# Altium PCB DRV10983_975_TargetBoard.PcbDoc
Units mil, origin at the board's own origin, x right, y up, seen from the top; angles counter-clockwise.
Board outline 2000 x 1750 mil, 2 copper layers (Top Layer, Bottom Layer), stack 64.8 mil thick; 30 components, 21 nets, 96 pads, 54 vias.
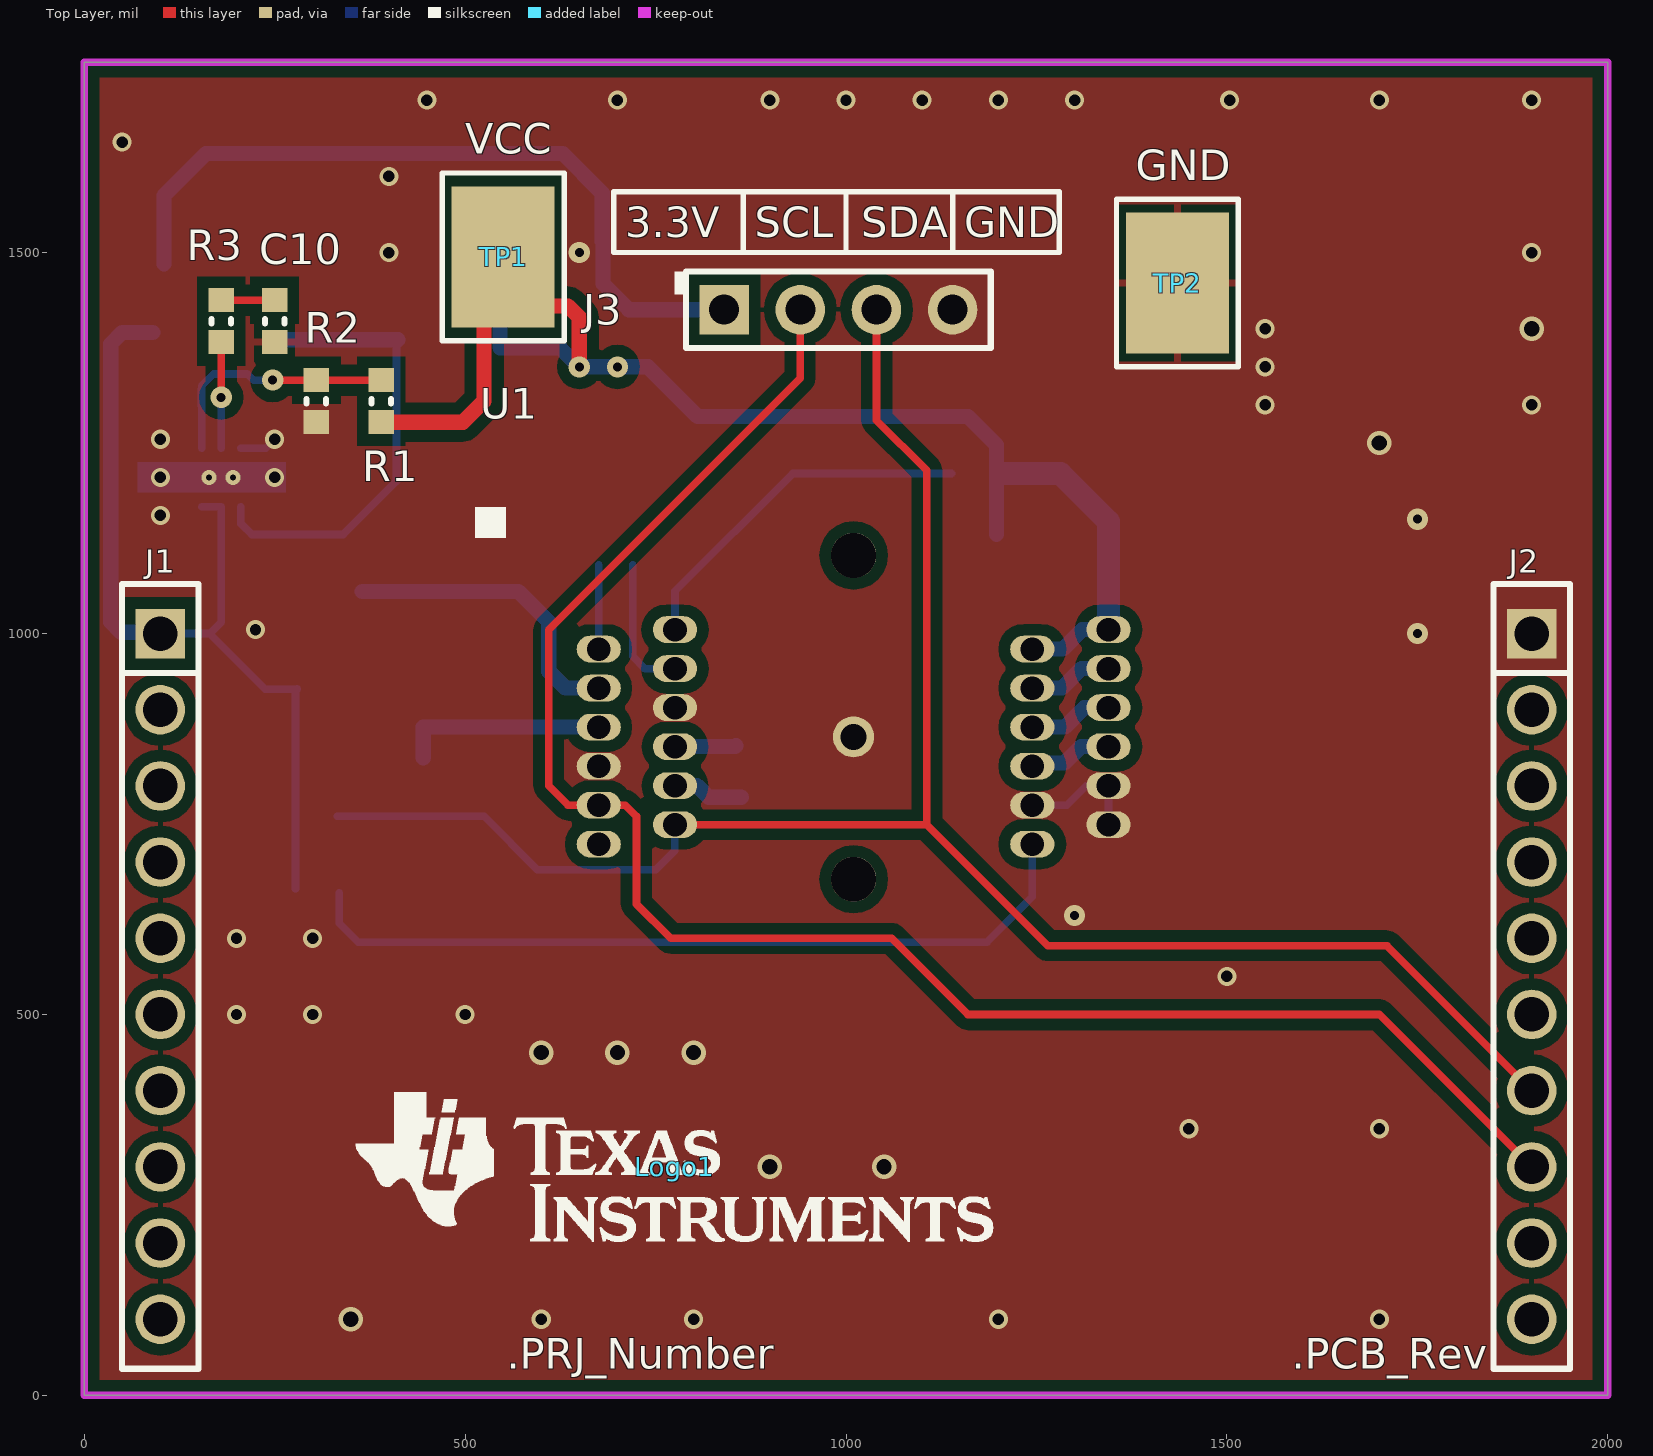
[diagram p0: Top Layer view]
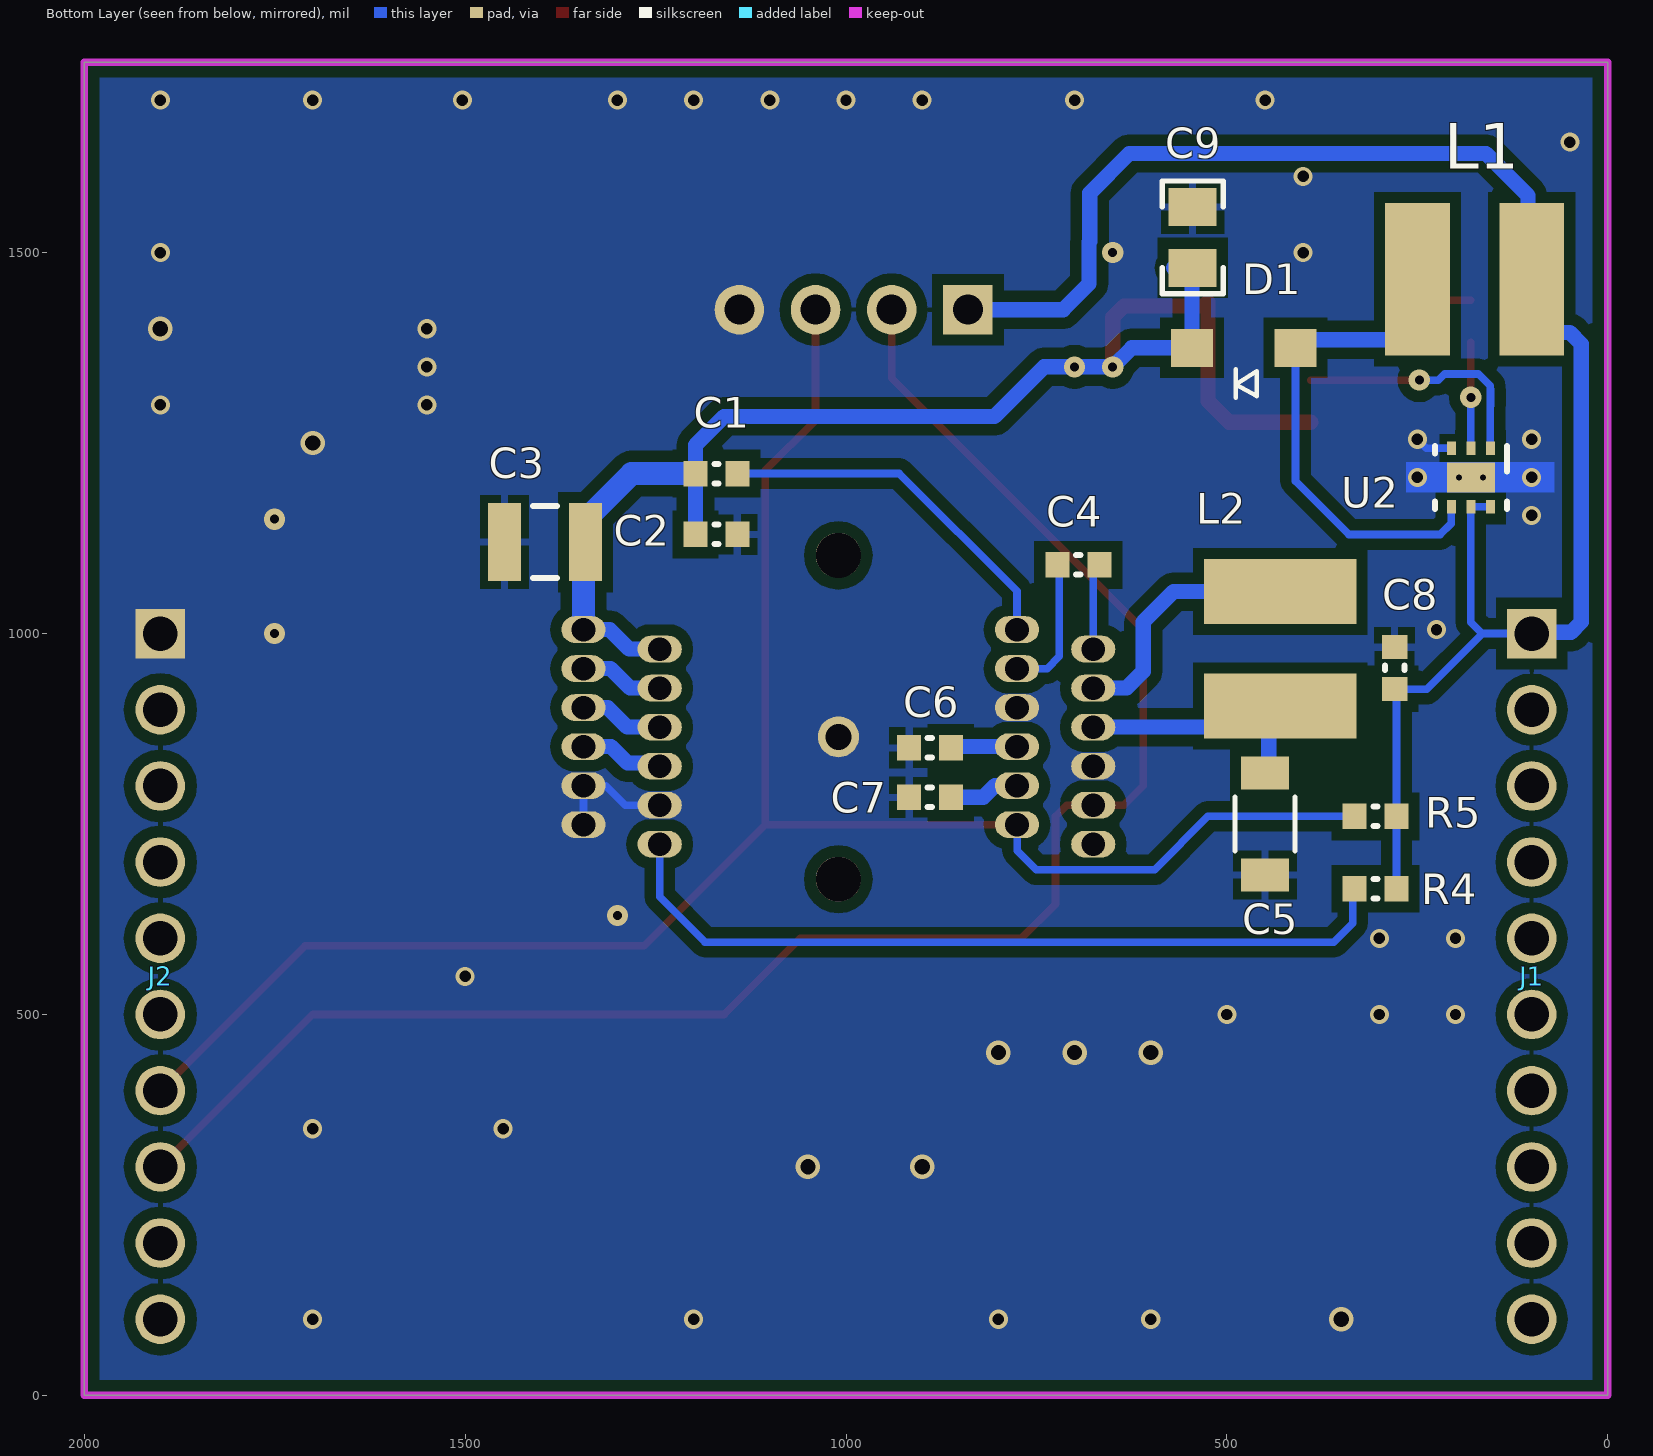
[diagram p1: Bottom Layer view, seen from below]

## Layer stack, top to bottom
Top Layer: signal copper 2.8
Dielectric: core 59.2, FR-4, Dk 4.8
Bottom Layer: signal copper 2.8

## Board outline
0,0 2000,0 2000,1750 0,1750

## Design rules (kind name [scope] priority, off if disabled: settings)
AcuteAngle [All] p1: minimum=4.50000000000000E+0001 checktracksonly=FALSE
AssemblyTestPointUsage [All] p1: valid=2
Clearance Clearance_BoardEdge_MountingHoles [OnCopper and InComponentClass('Mounting Holes') vs IsKeepOut] p1: gap=15
Clearance Clearance_BoardEdge_Poly [OnCopper and InPoly vs IsKeepOut] p2: gap=15
Clearance Clearance_BoardEdge [OnCopper and Not InComponentClass('Logo') and not InComponentClass('FiducialMark') and not InRegion(1000,500,4000,800) and Not IsKeepout vs IsKeepOut] p3: gap=15
Clearance Clearance_Poly [InPolygon] p4: gap=15
Clearance [All] p5: gap=7
ComponentClearance ComponentClearance_Logo [InComponentClass(Logo)] p1: gap=10 collisioncheckmode=3 verticalgap=10 showdistances=FALSE
ComponentClearance ComponentClearance_ScrewToNut [(HasFootprint('NY PMS 440 0025 PH')) vs (HasFootprint('Keystone_1902C'))] p2: gap=5 collisioncheckmode=3 verticalgap=10 showdistances=FALSE
ComponentClearance ComponentClearance_MountingHoles [InComponentClass('Mounting Holes')] p3: gap=250 collisioncheckmode=3 verticalgap=100000 showdistances=FALSE
ComponentClearance ComponentClearance_SmallPassives [HasFootprint('0201*') or HasFootprint('0402*') or HasFootprint('0508') or HasFootprint('0603*') or HasFootprint('0612') or HasFootprint('0805*') or HasFootprint('0815*') or HasFootprint('0830*') or HasFootprint('1206*') or HasFootprint('1210*') or HasFootprint('1808*') or HasFootprint('1812*') or HasFootprint('1825*') or HasFootprint('2010*') or HasFootprint('2220*') or HasFootprint('2225*') or HasFootprint('2512*') or HasFootprint('2728*') or HasFootprint('3518*') vs HasFootprint('0201*') or HasFootprint('0402*') or HasFootprint('0508') or HasFootprint('0603*') or HasFootprint('0612') or HasFootprint('0805*') or HasFootprint('0815*') or HasFootprint('0830*') or HasFootprint('1206*') or HasFootprint('1210*') or HasFootprint('1808*') or HasFootprint('1812*') or HasFootprint('1825*') or HasFootprint('2010*') or HasFootprint('2220*') or HasFootprint('2225*') or HasFootprint('2512*') or HasFootprint('2728*') or HasFootprint('3518*')] p4: gap=10 collisioncheckmode=3 verticalgap=10 showdistances=FALSE
ComponentClearance ComponentClearance_THtoSMT [IsThruComponent vs IsSMTComponent] p5: gap=100 collisioncheckmode=3 verticalgap=30 showdistances=FALSE
ComponentClearance ComponentClearance_THtoTH [IsThruComponent vs IsThruComponent] p6: gap=0 collisioncheckmode=3 verticalgap=0 showdistances=FALSE
ComponentClearance [All] p7: gap=10 collisioncheckmode=3 verticalgap=10 showdistances=FALSE
DiffPairsRouting [All] p1: maxlimit=100 minlimit=10 mostfreqgap=10 maxuncoupledlength=1000
FabricationTestPointUsage TestPointUsage [All] p1: valid=2 allowmultiple=FALSE
FabricationTestpoint Testpoint [All] p1: side=3 testpointundercomponent=TRUE minsize=40 maxsize=100 preferedsize=60 minholesize=0 maxholesize=40 preferedholesize=32 testpointgrid=1 allowsidetop=TRUE allowsidebottom=TRUE usegrid=TRUE gridtolerance=0.01
FanoutControl Fanout_LCC [IsLCC] p1: bgadir=Out bgaviamode=Centered fanoutstyle=Auto fanoutdirection=Alternating viagrid=1 // Fanout_LCC (Default Rule)
FanoutControl Fanout_BGA [IsBGA] p2: bgadir=Out bgaviamode=Centered fanoutstyle=Auto fanoutdirection=Alternating viagrid=1 // Fanout_BGA (Default Rule)
FanoutControl Fanout_Default [All] p4: bgadir=Out bgaviamode=Centered fanoutstyle=Auto fanoutdirection=Alternating viagrid=1 // Fanout_Default (Default Rule)
FanoutControl Fanout_Small [(CompPinCount < 5)] p5: bgadir=Out bgaviamode=Centered fanoutstyle=Auto fanoutdirection=OutThenIn viagrid=1 // Fanout_Small (Default Rule)
HoleSize [All] p1: absolutevalues=TRUE maxlimit=251 minlimit=8 maxpercent=80.000 minpercent=20.000
MinimumAnnularRing [All] p1: minimumring=5
MinimumSolderMaskSliver MinimumSolderMaskSliver_Logo [InComponentClass('Logo') vs InComponentClass('Logo')] p1: minsoldermaskwidth=0.7
MinimumSolderMaskSliver [All] p2: minsoldermaskwidth=3
PlaneClearance [All] p1: clearance=15
PlaneConnect [All] p1: planeconnectstyle=Relief reliefexpansion=10 reliefentries=4 reliefconductorwidth=10 reliefairgap=10
PolygonConnect PolygonConnect_1 [IsNamedPolygon('GND_TOP') or IsNamedPolygon('GND_BOT') vs Not (InComponent('U1') or InComponent('J2') or InComponent('J3') or InComponent('J5') or InComponent('C1') or InComponent('R1') or InComponent('R2') or IsStitchingVia or IsVia)] p1: connectstyle=Relief reliefconductorwidth=10 reliefentries=4 polygonreliefangle="90 Angle" airgapwidth=10
PolygonConnect [All] p2: connectstyle=Direct reliefconductorwidth=10 reliefentries=4 polygonreliefangle="90 Angle" airgapwidth=10
RoutingVias [All] p1: holewidth=15 width=25 viastyle="Through Hole" minholewidth=8 minwidth=20 maxholewidth=40 maxwidth=65
SMDToCorner [All] p1: distance=30000
SilkToSilkClearance [All] p1: silktosilkclearance=5
SilkscreenOverComponentPads [All] p1: minsilkscreentomaskgap=5
SolderMaskExpansion [All] p1: expansion=3
Width [All] p1: maxlimit=100 minlimit=6 preferedwidth=10 checkconnectedcopper=TRUE
13 further rules are at their usual default settings.

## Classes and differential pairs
component class Hardware_ANSI-B: !PCB Logo1 ZZ1 ZZ2 ZZ3 ZZ4
component class AssemblyNote: ZZ1 ZZ2 ZZ3 ZZ4
component class Header: J3
component class DRV10983_975_TargetBoard: C1 C2 C3 C4 C5 C6 C7 C8 C9 C10 D1 J1 J2 J3 L1 L2 R1 R2 R3 R4 R5 TP1 TP2 U1 U2
component class Logo: Logo1

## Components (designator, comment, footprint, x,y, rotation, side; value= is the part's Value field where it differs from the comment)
C1 "C1608X7R1H104K" 0603L 1170,1210 r180 bottom
C2 "C1608X7R1H104K" 0603L 1170,1130 r180 bottom
C3 "GRM32ER71H475KA88L" 1210L 1395,1120 r180 bottom
C4 "C1608X7R1H104K" 0603L 695,1090 r0 bottom
C5 "CGA5L3X5R1H106K160AB" 1206_190 450,750 r90 bottom
C6 "GRM188R61H105KAALD" 0603L 890,850 r180 bottom
C7 "GRM188R61H105KAALD" 0603L 890,785 r180 bottom
C8 "0603ZD475KAT2A" 0603L 280,955 r90 bottom
C9 "C2012X5R1H475K125AB" 0805_HV 545,1520 r90 bottom
C10 "C1608X7R1H103K" 0603L 250,1410 r270 top
D1 "D_SCHOT_MBR0540T" SOD-123 475,1375 r180 bottom
J1 "CRD-081413-B-T" CONN_SSW-110-23-F-S 100,1000 r90 bottom
J2 "CRD-081413-B-T" CONN_SSW-110-23-F-S 1900,1000 r90 bottom
J3 "5-146278-4" TE_5-146278-4 990,1425 r0 top
L1 "VLCF5020T-100M1R1-1" IND_VLCF5020T 175,1465 r0 bottom
L2 "VLCF5020T-100M1R1-1" IND_VLCF5020T 430,980 r90 bottom
Logo1 "Texas Instruments" TI_Stacked_Overlay_Small 775,300 r0 top
R1 "RC0603FR-07178KL" 0603L 390,1305 r270 top
R2 "CRCW060310K0FKEA" 0603L 305,1305 r90 top
R3 "CRCW060310K0FKEA" 0603L 180,1410 r270 top
R4 "CRCW06035K10JNEA" 0603L 305,665 r180 bottom
R5 "CRCW06035K10JNEA" 0603L 305,760 r180 bottom
TP1 "5016" Testpoint_Keystone_Compact 550,1494.41 r90 top
TP2 "5016" Testpoint_Keystone_Compact 1435,1460 r90 top
U1 "OTS-24(28)-0.65-02" RECEPTACLE_OTS_24(28)-0.65-01_WCENTERPIN 1010,890 r0 top
U2 "TPS61170DRV" DRV0006A 180,1205 r270 bottom
ZZ1 "This Assembly Note is for PCB labels only" AssemblyNoteLabel 170,2750 r0 top
ZZ2 "These assemblies are ESD sensitive, ESD precautions shall be observed." AssemblyNote 170,2540 r0 top
ZZ3 "These assemblies must be clean and free from flux and all contaminants. Use of no clean flux is not acceptable." AssemblyNote 170,2330 r0 top
ZZ4 "These assemblies must comply with workmanship standards IPC-A-610 Class 2, unless otherwise specified." AssemblyNote 170,2135 r0 top

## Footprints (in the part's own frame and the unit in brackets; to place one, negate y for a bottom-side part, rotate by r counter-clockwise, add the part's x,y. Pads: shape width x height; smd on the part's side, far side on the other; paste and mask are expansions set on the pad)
0603L [mm] "0603 from SM-752 data"
  rect 0.8x0.85 smd: 1(-0.7,0) 2(0.7,0)
  silkscreen extent -0.07,-0.33 0.07,0.33, body extent -0.87,-0.47 0.87,0.47, height 0.85
0805_HV [mil] "0805 with 30mil clearance between pads"
  rect 50x63 smd: 1(-40,0) 2(40,0)
  silkscreen extent -74,-40 74,40, body extent -43,-29 43,29, height 43
1206_190 [mm] "1206_190"
  rect 1.1x1.6 smd: 1(-1.7,0) 2(1.7,0)
  silkscreen extent -0.9,-1 0.9,1, body extent -1.75,-0.95 1.75,0.95, height 1.9
1210L [mm] "1210 from SM-752 data"
  rect 1.1x2.6 smd: 1(-1.35,0) 2(1.35,0)
  silkscreen extent -0.4,-1.2 0.4,1.2, body extent -1.7,-1.35 1.7,1.35, height 1.35
AssemblyNote [mil] "Assembly Note"
AssemblyNoteLabel [mil] "Assembly Note for PCB Labels"
CONN_SSW-110-23-F-S [mm] "SAMTEC"
  rect 1.65x1.65 hole 1.15: 1(0,0)
  round 1.65 hole 1.15: 2(-2.54,0) 3(-5.08,0) 4(-7.62,0) 5(-10.16,0) 6(-12.7,0) 7(-15.24,0) 8(-17.78,0) 9(-20.32,0) 10(-22.86,0)
  body extent -24.43,-1.27 1.57,1.27, height 8.59
DRV0006A [mm] "SON, 6-Leads, Body 2x2mm, Pitch 0.65mm, Thermal Pad 1.6x1mm, TI Recommended"
  rect 0.45x0.3 smd: 1(-0.975,0.65) 2(-0.975,0) 3(-0.975,-0.65) 4(0.975,-0.65) 5(0.975,0) 6(0.975,0.65)
  rect 1x1.6 smd paste-0.5: 7(0,0)
  silkscreen extent -1.05,-1.2 1.05,1.2, body extent -1.05,-1.05 1.05,1.05, height 0.81
IND_VLCF5020T [mil]
  rect 85x200 smd: 1(-75,0) 2(75,0)
RECEPTACLE_OTS_24(28)-0.65-01_WCENTERPIN [mil]
  oval 58x35 hole 31: 1(-234.5,115.2) 2(-334.5,89.6) 3(-234.5,64) 4(-334.5,38.4) 5(-234.5,12.8) 6(-334.5,-12.8) 7(-234.5,-38.4) 8(-334.5,-64) 9(-234.5,-89.6) 10(-334.5,-115.2) 11(-234.5,-140.8) 12(-334.5,-166.4) 13(234.5,-166.4) 14(334.5,-140.8) 15(234.5,-115.2) 16(334.5,-89.6) 17(234.5,-64) 18(334.5,-38.4) 19(234.5,-12.8) 20(334.5,12.8) 21(234.5,38.4) 22(334.5,64) 23(234.5,89.6) 24(334.5,115.2)
  round 59 hole 59 unplated: 25(0,-212.5) 26(0,212.5)
  round 54 hole 34: 27(0,-25.59)
  silkscreen extent -496,236 -456,276
SOD-123 [mil]
  rect 55x50 smd: 1(-71,0) 2(65,0)
  silkscreen extent -14,-66 14,-28
TE_5-146278-4 [mm] "TE CONNECTIVITY"
  rect 1.65x1.65 hole 1: 1(-3.81,0)
  round 1.65 hole 1: 2(-1.27,0) 3(1.27,0) 4(3.81,0)
  silkscreen extent -5.46,-1.27 5.08,1.27, body extent -4.95,-1.17 4.95,1.17, height 8.13
Testpoint_Keystone_Compact [mil] "Compact SMT test point"
  rect 185x135 smd: 1(0,0)
  silkscreen extent -110,-80 110,80, body extent -75,-56 75,56, height 91
TI_Stacked_Overlay_Small [mil]
  silkscreen extent -418,-98 418,98

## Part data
C1 C2 C4: "CAP, CERM, 0.1uF, 50V, +/-10%, X7R, 0603"
C3: "CAP, CERM, 4.7uF, 50V, +/-10%, X7R, 1210"
C5: "CAP, CERM, 10uF, 50V, +/-10%, X5R, 1206_190"
C6 C7: "CAP, CERM, 1uF, 50V, +/-10%, X5R, 0603"
C8: "CAP, CERM, 4.7uF, 10V, +/-10%, X5R, 0603"
C9: "CAP, CERM, 4.7uF, 50V, +/-10%, X5R, 0805"
C10: "CAP, CERM, 0.01uF, 50V, +/-10%, X7R, 0603"
D1: "Diode, Schottky, 0.5A, 40V"
J1 J2: library part SSW-110-23-F-S, "Connector, Receptacle, 100mil, 10x1, TH"
J3: "Header, 100mil, 4x1, Tin, TH"
L1 L2: library part IND_VLCF5020T-SERIES, "Inductor, SMT, yyA, zzmilliohm"
Logo1: library part TI_Logo, "Texas Instrument Corporate Signature"
R1: "RES, 178k ohm, 1%, 0.1W, 0603"
R2 R3: "RES, 10.0k ohm, 1%, 0.1W, 0603"
R4 R5: "RES, 5.1k ohm, 5%, 0.1W, 0603"
TP1 TP2: "Test Point, Compact, SMT"
U1: library part Receptacle_OTS-24(28)-065-01, "Socket, 24 pin HTTOP no center pin"
U2: "1.2A High Voltage Boost Converter in 2x2mm QFN Package, DRV0006A"
ZZ1: library part AssemblyNoteLabel
ZZ2 ZZ3 ZZ4: library part AssemblyNote

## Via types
v1: diameter 25, hole 15, Top Layer to Bottom Layer, tented both sides, 36 vias
v2: diameter 27.81, hole 11.81, Top Layer to Bottom Layer, 8 vias
v3: diameter 32, hole 20, Top Layer to Bottom Layer, 8 vias
v4: diameter 19.68, hole 7.87, Top Layer to Bottom Layer, 2 vias

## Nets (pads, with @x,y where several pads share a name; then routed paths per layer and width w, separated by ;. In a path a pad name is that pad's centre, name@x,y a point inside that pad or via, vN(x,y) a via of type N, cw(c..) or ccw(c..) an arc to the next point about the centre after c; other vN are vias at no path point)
3.3V: C8.1 J1.1 J3.1 L1.1 R4.2 R5.2 U2.5 U2.6 | length 2150.9
  Bottom Layer w10: J1.1 165,1000 ; U2.6 U2.5 180,1015 165,1000 ; R4.2 R5.2 277.44,924.88 C8.1@279.51,926.95 ; C8.1@280,926.95 C8.1@279.51,926.95 ; C8.1 C8.1@279.51,926.95 ; 165,1000 238.05,926.95 C8.1@279.51,926.95
  Bottom Layer w20: J1.1@80,1001.61 48.39,1001.61 35,1015 35,1380 50,1395 L1.1@90,1395 ; L1.1@105,1485 105,1575 160,1630 628.28,1630 680,1578.28 680,1514.61 680.91,1513.71 680.91,1459.09 715,1425 J3.1
CPN: C4.2 U1.3 | length 182.1
  Bottom Layer w10: C4.2@720,1090 720,970 736,954 U1.3
CPP: C4.1 U1.2 | length 110.4
  Bottom Layer w10: U1.2 C4.1@675.5,1090
FG: U1.12
GND: C2.2 C3.1 C5.1 C6.1 C7.1 C8.2 C9.2 C10.2 J2.1 J3.4 R2.1 TP2.1 U1.5 U1.8 U1.14 U1.15 U1.16 U1.27 U2.3 U2.7 | length 224.9
  Bottom Layer w10: v4(195.75,1205) U2.7@205.59,1214.84 ; U2.3 238.39,1243.39 v1(250,1255) ; U1.15 1289.8,774.8 1315.4,800.4 U1.16 U1.14
  other v1: 600,100 800,100 1200,100 1700,100 1450,350 1700,350 200,500 300,500 500,500 1500,550 200,600 300,600 225,1005 100,1155 100,1205 250,1205 100,1255 1550,1300 1900,1300 1550,1350 1550,1400 400,1500 1900,1500 400,1600 50,1645 450,1700 700,1700 900,1700 1000,1700 1100,1700 1200,1700 1300,1700 1503.62,1700 1700,1700 1900,1700
  other v2: 1300,630 1750,1000 1750,1150 650,1500
  other v3: 350,100 900,300 1050,300 600,450 700,450 800,450 1700,1250 1900,1400
  other v4: 164.25,1205
NetC10_1: C10.1 R3.1 | length 70
  Top Layer w10: R3.1 C10.1
NetD1_2: D1.2 L1.2 U2.4 | length 581.6
  Bottom Layer w10: U2.4 205.59,1144.41 220,1130 340,1130 410,1200 D1.2
  Bottom Layer w20: L1.2@266.85,1385.5 D1.2@411.85,1385.5
NetR1_1: R1.1 R2.2 U2.1 | length 327.3
  Top Layer w10: v2(247.56,1332.56) R2.2 R1.1
  Bottom Layer w10: U2.1 154.41,1298.95 154.09,1299.27 154.09,1320.73 154.41,1321.05 154.41,1325 170.08,1340.67 214.33,1340.67 222.44,1332.56 v2(247.56,1332.56)
NetR3_2: R3.2 U2.2 | length 139.1
  Top Layer w10: v2(180,1310) R3.2
  Bottom Layer w10: U2.2 v2(180,1310)
SCL: J2.8 J3.2 U1.10 | length 2326.2
  Top Layer w10: J3.2 940,1335 610,1005 610,800 635.2,774.8 710.2,774.8 725,760 725,645 770,600 1060,600 1160,500 1700,500 J2.8
SDA: J2.7 J3.3 R5.1 U1.11 | length 2598.8
  Top Layer w10: 885.85,749.2 U1.11 1105.8,749.2 ; J3.3 1040,1280 1105.8,1214.21 1105.8,749.2 ; J2.7 1710,590 1265,590 1105.8,749.2
  Bottom Layer w10: R5.1 525,760 595,690 750,690 775,715 775,748.7 U1.11
SPEED: R4.1 U1.13 | length 1053.6
  Bottom Layer w10: R4.1@335,660 335,620 360,595 1185,595 1244.5,654.5 U1.13
SW: L2.2 U1.4 | length 401
  Bottom Layer w20: L2.2@365,1055 570,1055 610,1015 610,950 631.6,928.4 U1.4
U: U1.17 U1.18 | length 110.6
  Bottom Layer w20: U1.17 1248.5,830 1286.8,830 1308.4,851.6 U1.18
V: U1.19 U1.20 | length 110.6
  Bottom Layer w20: U1.19 1287.2,877.2 1312.8,902.8 U1.20
V1P8: C6.2 U1.7 | length 80.5
  Bottom Layer w20: U1.7 854.61,851.6 C6.2@855.57,852.56
V3P3: C7.2 U1.9 | length 93.3
  Bottom Layer w20: U1.9 804.6,800.4 820,785 C7.2
VCC: C1.1 C2.1 C3.2 C9.1 D1.1 R1.2 TP1.1 U1.23 U1.24 | length 1813.7
  Top Layer w20: R1.2 497.44,1277.44 525,1305 525,1435 530,1430 635,1430 650,1415 v2(650,1350)
  Bottom Layer w20: C9.1@546,1456 D1.1 625,1375 v2(650,1350) 740,1350 805,1285 1160,1285 1197.56,1247.44 C1.1 C2.1 ; C9.1@557.5,1467.5 C9.1@570,1480 ; U1.23 1284.6,979.6 1310.2,1005.2 U1.24
  Bottom Layer w30: C1.1@1204.43,1210 1281.38,1210 1344.5,1146.88 U1.24
  other v2: 700,1350
VCP: C1.2 U1.1 | length 477.3
  Bottom Layer w10: U1.1 775.5,1055.5 930,1210 C1.2@1138.5,1210
VREG: C5.2 L2.1 U1.6 | length 270.8
  Bottom Layer w20: C5.2@445,836.93 445,877.2 U1.6
W: U1.21 U1.22 | length 110.6
  Bottom Layer w20: U1.21 1283.4,928.4 1309,954 U1.22
pads on no net: J1.2 J1.3 J1.4 J1.5 J1.6 J1.7 J1.8 J1.9 J1.10 J2.2 J2.3 J2.4 J2.5 J2.6 J2.9 J2.10 U1.25 U1.26

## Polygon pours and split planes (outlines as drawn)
GND on Bottom Layer "GND_BOT" (solid, remove dead copper, pour order 5): 0,0 2000,0 2000,1750 0,1750
GND on Top Layer "GND_TOP" (solid, remove dead copper, pour order 32): 0,1750 2000,1750 2000,0 0,0

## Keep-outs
Keep-Out Layer:
  the board outline again, w10
  text ".Layer_Name" at 577,-858.49 h60

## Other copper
Top Layer:
  text ".Layer_Name" at 577,-858.49 h60
Bottom Layer:
  rectangle net GND: 70,1185 265,1225
  text ".Layer_Name" at 577,-858.49 h60

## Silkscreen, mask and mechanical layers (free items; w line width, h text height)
Top Overlay:
  lines w7: 865,1500 865,1580 ; 1000,1500 1000,1580 ; 1140,1500 1140,1580 ; 695,1500 695,1580 1280,1580 1280,1500 695,1500
  text "VCC" at 500,1630 h40
  text "GND" at 1380,1595 h40
  text "3.3V" at 710,1520 h40
  text "SCL" at 880,1520 h40
  text "SDA" at 1020,1520 h40
  text "GND" at 1155,1520 h40
  text ".PRJ_Number" at 555,35 h40
  text ".PCB_Rev" at 1585,35 h40
  text ".Layer_Name" at 577,-858.49 h60
Bottom Overlay:
  text ".Layer_Name" at 577,-858.49 h60
Top Paste:
  text ".Layer_Name" at 577,-858.49 h60
Bottom Paste:
  text ".Layer_Name" at 577,-858.49 h60
Top Solder:
  text ".Layer_Name" at 577,-858.49 h60
  text ".Layer_Name" at 577,-858.49 h60
Bottom Solder:
  text ".Layer_Name" at 577,-858.49 h60
Drill Guide:
  text ".Layer_Name" at 577,-858.49 h60
M1 Board Outline:
  the board outline again, w10
  text ".Layer_Name" at 577,-858.49 h60
M2 Board Dimensions:
  rectangle: 124.5,-410.5 499.5,-285.5
  rectangle: -0.5,-285.5 124.5,-160.5
  lines w7: -0.5,-285.5 999.5,-285.5 ; 124.5,-410.5 124.5,-160.5 ; 249.5,-410.5 249.5,-160.5 ; 499.5,-410.5 499.5,-160.5 ; 749.5,-410.5 749.5,-160.5 ; -0.5,-410.5 -0.5,-160.5 999.5,-160.5 999.5,-410.5 -0.5,-410.5
  lines w10: -0.5,-475.5 -0.5,-455.5 ; 59.5,-485.5 -0.5,-465.5 ; 59.5,-445.5 -0.5,-465.5 ; 223.58,-465.5 -0.5,-465.5 ; 775.42,-465.5 999.5,-465.5 ; 939.5,-485.5 999.5,-465.5 ; 939.5,-445.5 999.5,-465.5 ; 999.5,-475.5 999.5,-455.5
  text "1000 (mil)" at 233.58,-501.49 h60
  text ".Layer_Name" at 577,-858.49 h60
M3 3D STEP Top:
  text ".Layer_Name" at 577,-858.49 h60
M4 3D STEP Bottom:
  text ".Layer_Name" at 577,-858.49 h60
M5 Assembly Top:
  lines w7: 2319,170.5 3444,170.5 ; 2319,293 3441.5,293 ; 2634,50.5 2634,413 ; 3019,50.5 2319,50.5 ; 3019,413 2319,413 ; 2319,50.5 2319,413 ; 2319,50.5 3444,50.5 3444,413 2319,413
  lines w10: -292,-930.17 6308,-930.17 ; -292,-726.83 6310,-726.83 ; -292,-523.5 -292,-1133.5 3713,-1133.5 6310,-1133.5 6310,-523.5 -291.5,-523.5 -291.5,-1133.5 1284,-1133.5 ; 2173,-1133.5 2173,-523.5 ; 3440,-726.83 3440,-523.5 ; 4280,-726.83 4280,-523.5 ; 4902,-1140 4902,-937.17
  text "TABLE 1" at 2706.5,448 h40
  text "Variant" at 2344,338 h40
  text "Label text" at 2779,338 h40
  text "001" at 2411.5,218 h40
  text "ChangeMe!" at 2689,215.5 h40
  text "002" at 2411.5,93 h40
  text "ChangeMe!" at 2684,90.5 h40
  text "COMPONENTS MARKED 'DNP' SHOULD NOT BE POPULATED." at 1153.5,-318.5 h60
  text "ASSEMBLY VARIANT:" at 1153,-434 h60
  text ".VariantName" at 2189,-434 h60
  text "PCB VIEWED FROM TOP SIDE" at -228.5,-655.67 h60
  text "BOARD #:" at 2248,-655.67 h60
  text ".PRJ_Number" at 2793.5,-655.67 h60
  text "REV:" at 3638,-655.67 h60
  text ".PCB_Rev" at 3929.5,-655.67 h60
  text "SVN REV:" at 4476,-655.67 h60
  text ".VersionControl_RevNumber" at 4982,-655.67 h60
  text "IGNORE ->" at -228.5,-858.49 h60
  text "PLOT NAME =" at -228.5,-1064.34 h60
  text ".plot_File_Name" at 577,-1064.34 h60
  text "GENERATED    :" at 2250,-1064.34 h60
  text ".Print_Date" at 3119.5,-1064.34 h60
  text ".Print_Time" at 3848.5,-1064.34 h60
  text "TEXAS INSTRUMENTS" at 5113,-1064.34 h60
M6 Assembly Bottom:
  lines w10: -292.5,-727.33 6309.5,-727.33 ; -290.5,-930.67 6309.5,-930.67 ; 1115.5,-1140.5 1115.5,-937.67 ; 1737.5,-727.33 1737.5,-524 ; 2577.5,-727.33 2577.5,-524 ; 3844.5,-1134 3844.5,-524 ; 4733.5,-1134 6309,-1134 6309,-524 -292.5,-524 -292.5,-1134 2304.5,-1134 6309.5,-1134 6309.5,-524
  text "COMPONENTS MARKED 'DNP' SHOULD NOT BE POPULATED." at 6102,-318 h60
  text ".VariantName" at 5058,-434 h60
  text "ASSEMBLY VARIANT:" at 6097,-434 h60
  text ".VersionControl_RevNumber" at 1035.5,-656.17 h60
  text "SVN REV:" at 1541.5,-656.17 h60
  text ".PCB_Rev" at 2088,-656.17 h60
  text "REV:" at 2379.5,-656.17 h60
  text ".PRJ_Number" at 3224,-656.17 h60
  text "BOARD #:" at 3769.5,-656.17 h60
  text "PCB VIEWED FROM BOTTOM SIDE" at 6246,-656.17 h60
  text "IGNORE ->" at 2547.85,-858.49 h60
  text "TEXAS INSTRUMENTS" at 904.5,-1064.84 h60
  text ".Print_Time" at 2169,-1064.84 h60
  text ".Print_Date" at 2898,-1064.84 h60
  text "GENERATED    :" at 3767.5,-1064.84 h60
  text ".plot_File_Name" at 5440.5,-1064.84 h60
  text "PLOT NAME =" at 6246,-1064.84 h60
M9 Title Sheet:
  drawing of 57 lines, arcs and shapes, not listed
  text "1" at 739.84,8036.5 h70
  text "2" at 3235.5,8036.5 h70
  text "3" at 5724.84,8036.5 h70
  text "4" at 8231.51,8036.5 h70
  text "5" at 10730.5,8036.5 h70
  text "6" at 13235.5,8036.5 h70
  text "A" at -416.5,6893.5 h70
  text "A" at 14383.5,6893.5 h70
  text "B" at -416.5,4513.5 h70
  text "B" at 14383.5,4513.5 h70
  text "C" at -416.5,2138.5 h70
  text "C" at 14383.5,2138.5 h70
  text "PROJECT TITLE:" at 11343.5,277.5 h45
  text ".PRJ_Title" at 11393.5,144.17 h70
  text "DESIGNED FOR:" at 11343.5,-23.5 h45
  text ".PRJ_Customer" at 11393.5,-163.5 h70
  text "D" at -416.5,-231.5 h70
  text "D" at 14383.5,-231.5 h70
  text "FILE NAME:" at 11343.5,-323.5 h45
  text ".PCB_File_Name_No_Path" at 11393.5,-443.5 h70
  text "Texas Instruments (TI) and/or its licensors do not warrant the accuracy or completeness of this specification" at 6374,-605.34 h45
  text "ENGINEER:" at 11343.5,-613.5 h45
  text "LAYOUT BY:" at 12848.5,-613.5 h45
  text "or any information contained therein. TI and/or its licensors do not warrant that this design will meet" at 6329.01,-718 h45
  text ".PRJ_Engineer" at 11393.5,-768.49 h70
  text ".PCB_Layout" at 12899,-768.49 h70
  text "the specifications, will be suitable for your application or fit for any particular purpose, or will operate in" at 6329.01,-830.67 h45
  text ".Layer_Name" at 577,-858.49 h60
  text "ALTIUM DESIGNER VERSION:" at 12848.5,-923.5 h45
  text "an implementation. TI and/or its licensors do not warrant that the design is production worthy. You should" at 6329.01,-943.33 h45
  text "completely validate and test your design implementation to confirm the system functionality for your application." at 6374,-1056 h45
  text ".print_Scale" at 11393.5,-1056.83 h70
  text ".Application_BuildNumber" at 12899,-1056.83 h70
  text "1" at 739.84,-1263.5 h70
  text "2" at 3235.5,-1263.5 h70
  text "3" at 5724.84,-1263.5 h70
  text "4" at 8231.51,-1263.5 h70
  text "5" at 10730.5,-1263.5 h70
  text "6" at 13235.5,-1263.5 h70
M10 Fab Notes:
  drawing of 212 lines, arcs and shapes, not listed
  text "DESIGN INFORMATION" at 12381.02,6810 h60
  text "(REFER ALSO ARRAY/PANEL PROFILING INFORMATION)" at 12019.46,6648.29 h60
  text "BOARD SIZE" at 11333.46,6644 h60
  text "2000MIL" at 11795.78,6516.18 h60
  text "X" at 12301.46,6516.18 h60
  text "1750MIL" at 12532.78,6516.18 h60
  text "Number of Layers :" at 11736.46,6319 h60
  text "2" at 12831.27,6309 h60
  text "MIN. TRACK WIDTH:" at 11736.46,6180 h60
  text "8" at 12832.7,6180 h60
  text "MIL" at 12987.46,6180 h60
  text "MIN. CLEARANCE:" at 11736.46,6048 h60
  text "8" at 12832.7,6048 h60
  text "MIL" at 12987.46,6048 h60
  text "MIN. VIA PAD SIZE:" at 11736.46,5916 h60
  text "24" at 12802.71,5916 h60
  text "MIL" at 12987.46,5916 h60
  text "0.05mm (2MIL)" at 12431.46,5774.29 h60
  text "MINIMUM ANNULAR RING" at 11407.23,5770 h60
  text "EXTERNAL" at 13139.46,5770 h60
  text "PER" at 11607.23,5652 h60
  text "IPC-D-275 CLASS 2 LEVEL C" at 11827.23,5652 h60
  text "MIL, HOLES" at 13315.46,5539.71 h60
  text "+/-" at 12923,5539 h60
  text "+/-" at 13777,5539 h60
  text "REGISTRATION TOLERANCES:" at 11407.23,5534 h60
  text "METAL" at 12607,5534 h60
  text "5" at 13183.2,5534 h60
  text "3" at 14016.2,5534 h60
  text "MIL" at 14132.46,5534 h60
  text "MATERIAL:" at 11332.46,5324.54 h60
  text "FR-4 High Tg" at 12318.9,5184.21 h60
  text "FR-408" at 11753.46,5175.64 h60
  text "X" at 12165.46,5175.64 h60
  text "OTHER" at 13241.46,5175.64 h60
  text "62 MIL (1.6mm) +/-10%" at 12073.56,5012.92 h60
  text "THICKNESS:" at 11407.23,5008.64 h60
  text "X" at 11945.4,5008.64 h60
  text "OTHER" at 13358.46,5008.64 h60
  text "TOLERANCE:" at 11407.23,4850.64 h60
  text "X" at 12246.53,4850.64 h60
  text "ANSI IPC-6012 TYPE 3 CLASS 2" at 12433.48,4850.64 h60
  text "OTHER +/-" at 12433.46,4694.64 h60
  text "BOW & TWIST:" at 11407.23,4537.64 h60
  text "X" at 12246.53,4537.64 h60
  text "ANSI IPC-6012 TYPE 3 CLASS 2" at 12433.48,4537.64 h60
  text "OTHER +/-" at 12433.46,4379.13 h60
  text "COPPER THICKNESS (FINISHED):" at 11332.46,4243.64 h60
  text "1.4MIL (1oz)" at 12212.46,4090.92 h60
  text "2MIL (1.4oz)" at 12979.46,4090.92 h60
  text "2.8MIL (2oz)" at 13706.46,4090.92 h60
  text "OUTER:" at 11689.46,4086.64 h60
  text "X" at 12085,4080 h60
  text "X" at 12085,3935 h60
  text "1.4MIL (1oz)" at 12212.46,3933.92 h60
  text "2.8MIL (2oz)" at 12979.46,3933.92 h60
  text "N/A" at 13706,3934.29 h60
  text "INNER SIGNAL:" at 11400.38,3929.64 h60
  text "DRILLING:" at 11332.46,3790.64 h60
  text "REFERENCE:" at 11407.23,3673.64 h60
  text "X" at 12055.46,3673.64 h60
  text "AS SHOWN" at 12242.46,3673.64 h60
  text "X" at 12956.46,3673.64 h60
  text "NC_DRILL FILES" at 13093.46,3673.64 h60
  text "PTH MIN COPPER THICKNESS:" at 11407.23,3515.64 h60
  text "X" at 12757.46,3515.64 h60
  text "1MIL" at 12894.46,3515.64 h60
  text "OTHER" at 13391.46,3515.64 h60
  text "BOARD FINISH:" at 11332.46,3356.64 h60
  text "SILKSCREEN:" at 11487.68,3238.64 h60
  text "X" at 12436.46,3238.64 h60
  text "TOP" at 12562.46,3238.64 h60
  text "X" at 12946.46,3238.64 h60
  text "BOTTOM" at 13073.46,3238.64 h60
  text "SILKSCREEN COLOR:" at 11487.68,3071.64 h60
  text "X" at 12435.42,3071.64 h60
  text "WHITE" at 12562.46,3071.64 h60
  text "OTHER" at 13073.46,3071.64 h60
  text "SOLDER RESIST COLOR:" at 11487.68,2901.64 h60
  text "GREEN" at 12182.46,2742.44 h60
  text "BLUE" at 12773.46,2742.44 h60
  text "OTHER" at 13311.46,2742.44 h60
  text "X" at 13160,2740 h60
  text "RED" at 13860,2740 h60
  text "IMMERSION GOLD (ENIG)" at 12393.46,2553.92 h60
  text "ENEPIG" at 13731,2550.64 h60
  text "SURFACE FINISH:" at 11332.46,2549.64 h60
  text "IMM. TIN/SILVER OR EQUIV" at 11662,2392.64 h60
  text "OTHER" at 13093.46,2392.64 h60
  text "X" at 11500,2390 h60
  text "ARRAY/PANEL:" at 11332.46,2213.64 h60
  text "CUT AND TRIM PER MECH LAYER 1" at 12393.46,2209.35 h60
  text "N.C. ROUTE" at 12393.46,2057.64 h60
  text "X" at 13072.46,2057.64 h60
  text "V. SCORE" at 13259.46,2057.64 h60
  text "CERTIFICATION:" at 11332.46,1920.64 h60
  text "MATERIALS AND WORKMANSHIP FOR ALL PCBS" at 12057.46,1920.64 h60
  text "TO MEET OR EXCEED THE REQUIREMENTS OF:" at 12057.46,1822.64 h60
  text "X" at 11683.96,1686.13 h60
  text "ANSI IPC-A-600F CLASS ->" at 11822.96,1686.13 h60
  text "X" at 13462.02,1686.13 h60
  text "2" at 13580.96,1686.14 h60
  text "1" at 13265.96,1684.64 h60
  text "3" at 13934.96,1684.64 h60
  text "X" at 11686.02,1526.64 h60
  text "UL 94V-0" at 11822.96,1526.64 h60
  text "X" at 12498.02,1526.64 h60
  text "RoHS" at 12634.96,1526.64 h60
  text "OTHER" at 13279.36,1526.64 h60
  text "PER ORDER" at 13676.42,1526.64 h60
  text "ADDITIONAL REQUIREMENTS:" at 11332.46,1385.64 h60
  text "MICROSECTION:" at 11407.23,1270.64 h60
  text "YES" at 12312.96,1270.64 h60
  text "REQUIRED" at 13174.46,1114.49 h60
  text "BARE BOARD ELEC. TEST:" at 11407.23,1111.64 h60
  text "NONE" at 12712.96,1111.64 h60
  text "PER ORDER" at 13766.46,1111.64 h60
  text "X" at 13640,1110 h60
  text "MANUFACTURER'S UL:" at 11407.23,954.64 h60
  text "RAIL" at 12572.96,950.35 h60
  text "METAL" at 13064.77,950.35 h60
  text "X" at 13440,950 h60
  text "SILK" at 13576.46,950.35 h60
  text ".Layer_Name" at 577,-858.49 h60
M11 Gerber Information:
  lines w10: -292,-930.17 6308,-930.17 ; -292,-726.83 6310,-726.83 ; -292,-523.5 -292,-1133.5 3713,-1133.5 6310,-1133.5 6310,-523.5 -291.5,-523.5 -291.5,-1133.5 1284,-1133.5 ; 2173,-1133.5 2173,-523.5 ; 3440,-726.83 3440,-523.5 ; 4280,-726.83 4280,-523.5 ; 4902,-1140 4902,-937.17
  text "ALL ARTWORK VIEWED FROM TOP SIDE" at -228.5,-655.67 h60
  text "BOARD #:" at 2248,-655.67 h60
  text ".PRJ_Number" at 2793.5,-655.67 h60
  text "REV:" at 3638,-655.67 h60
  text ".PCB_Rev" at 3929.5,-655.67 h60
  text "SVN REV:" at 4476,-655.67 h60
  text ".VersionControl_RevNumber" at 4982,-655.67 h60
  text "LAYER NAME =" at -228.5,-858.49 h60
  text "PLOT NAME =" at -228.5,-1064.34 h60
  text ".plot_File_Name" at 577,-1064.34 h60
  text "GENERATED    :" at 2250,-1064.34 h60
  text ".Print_Date" at 3119.5,-1064.34 h60
  text ".Print_Time" at 3848.5,-1064.34 h60
  text "TEXAS INSTRUMENTS" at 5113,-1064.34 h60
M12 Stackup:
  lines w6: 11360,7460 13910,7460 ; 11360,7564.4 13910,7564.4 ; 11300,6975 ccw(c11334,6975) 11334,6941 13936,6941 ccw(c13936,6975) 13970,6975 13970,7681 ccw(c13936,7681) 13936,7715 11334,7715 ccw(c11334,7681) 11300,7681 11300,6975
  text "The Stackup Legend below this is static." at 11605.5,7874.5 h60
  text "If you change the stackup, update the Legend." at 11615.5,7784.5 h60
  text "Layer Stack Up Detail for: Ref_Design.PcbDoc" at 11360,7597.1 h57
  text "Layer" at 11360,7525.4 h24
  text "Gerber" at 12255.81,7525.4 h24
  text "Copper" at 12819.33,7525.4 h24
  text "Dielectric" at 13422.04,7525.4 h24
  text "Name" at 11360,7477.4 h24
  text "Document" at 12255.81,7477.4 h24
  text "Thickness" at 12819.33,7477.4 h24
  text "Material" at 13422.04,7477.4 h24
  text "Top Solder Mask" at 11360,7384.44 h34
  text "(.GTS)" at 12255.81,7384.44 h34
  text "Solder Resist" at 13422.04,7384.44 h34
  text "Top Layer" at 11360,7287.69 h34
  text "(.GTL)" at 12255.81,7287.69 h34
  text "1.4mil" at 12819.33,7287.69 h34
  text "FR-4" at 13422.04,7239.31 h34
  text "Bottom Layer" at 11360,7190.94 h34
  text "(.GBL)" at 12255.81,7190.94 h34
  text "1.4mil" at 12819.33,7190.94 h34
  text "Bottom Solder Mask" at 11360,7094.19 h34
  text "(.GBS)" at 12255.81,7094.19 h34
  text "Solder Resist" at 13422.04,7094.19 h34
  text ".Layer_Name" at 577,-858.49 h60
M13 Component Bodies Top:
  text ".Layer_Name" at 577,-858.49 h60
M14 Component Bodies Bottom:
  text ".Layer_Name" at 577,-858.49 h60
M15 Courtyards Top:
  text ".Layer_Name" at 577,-858.49 h60
M16 Courtyards Bottom:
  text ".Layer_Name" at 577,-858.49 h60
Drill Drawing:
  text ".legend" at 2302.5,785.5 h60
  text "Drill Table" at 2327.5,600.5 h60
  text ".Layer_Name" at 577,-858.49 h60

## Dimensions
0,0 to 2000,0 on M2 Board Dimensions
0,0 to 0,1750 on M2 Board Dimensions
